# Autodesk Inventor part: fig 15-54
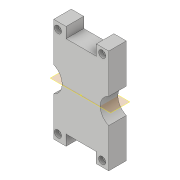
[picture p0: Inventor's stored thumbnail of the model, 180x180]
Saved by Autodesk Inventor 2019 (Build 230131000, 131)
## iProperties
Created: 2018-03
Part Number: fig 15-54
Material: Generic
Document SubType Name: Modeling
Designer: CADCIM 00
Density: 1 g/cm^3
Appearance: Default
Author: CADCIM 00
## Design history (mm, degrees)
sketch "Sketch1"
  geometry: L1 (-7.807, 14.718)-(-4.287, 14.718); L2 (-4.287, 14.718)-(-4.287, 11.71); L3 (-4.287, 11.71)-(0, 11.71); L4 (0, 11.71)-(0, 0); L5 (0, 0)-(-9.279, 0); L6 (-7.807, 14.718)-(-7.807, 3.593); L7 (-7.807, -14.718)-(-4.287, -14.718); L8 (-4.287, -14.718)-(-4.287, -11.71); L9 (-7.807, -14.718)-(-7.807, -3.593); L10 (-4.287, -11.71)-(0, -11.71); L11 (7.807, 14.718)-(4.287, 14.718); L12 (4.287, 14.718)-(4.287, 11.71); L13 (7.807, 14.718)-(7.807, 3.593); L14 (7.807, -14.718)-(4.287, -14.718); L15 (4.287, -14.718)-(4.287, -11.71); L16 (7.807, -14.718)-(7.807, -3.593); L17 (4.287, 11.71)-(0, 11.71); L18 (4.287, -11.71)-(0, -11.71); A1 r 3.882 centre (-9.279, 0) between (-5.396, 0) and (-7.807, 3.593); A2 r 3.882 centre (-9.279, 0) between (-7.807, -3.593) and (-5.396, 0); A3 r 3.882 centre (9.279, 0) between (7.807, 3.593) and (5.396, 0); A4 r 3.882 centre (9.279, 0) between (5.396, 0) and (7.807, -3.593); 1 further point
  constraints: 36 end point, 16 symmetric about line, 8 point on circle, 4 centre point, 3 perpendicular, 2 coincident, 2 horizontal, 1 point on line, 1 vertical, 3 other
extrude "Extrusion1" new body sketch "Sketch1" distance "d0" = 5; taper "d1" = 0 deg
sketch "Sketch2"
  geometry: 1 further point
sketch "Sketch3"
  geometry: 3 further points
hole "Hole1" sketch "Sketch3" at (-6.585, 12.819), (5.959, 13.07) diameter "d2" = 1; stored, may be unused: countersink angle "d6" = 90 deg, drill point angle "d8" = 118 deg; dims "d3" = 6, "d4" = 2, "d5" = 1, "d7" = 8
workplane "Work Plane1"
mirror "Mirror1"
body "Solid1"
